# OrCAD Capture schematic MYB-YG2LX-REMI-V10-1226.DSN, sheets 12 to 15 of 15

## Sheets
12 PH-RPI & KEY & RTC: size A3; note: MISC
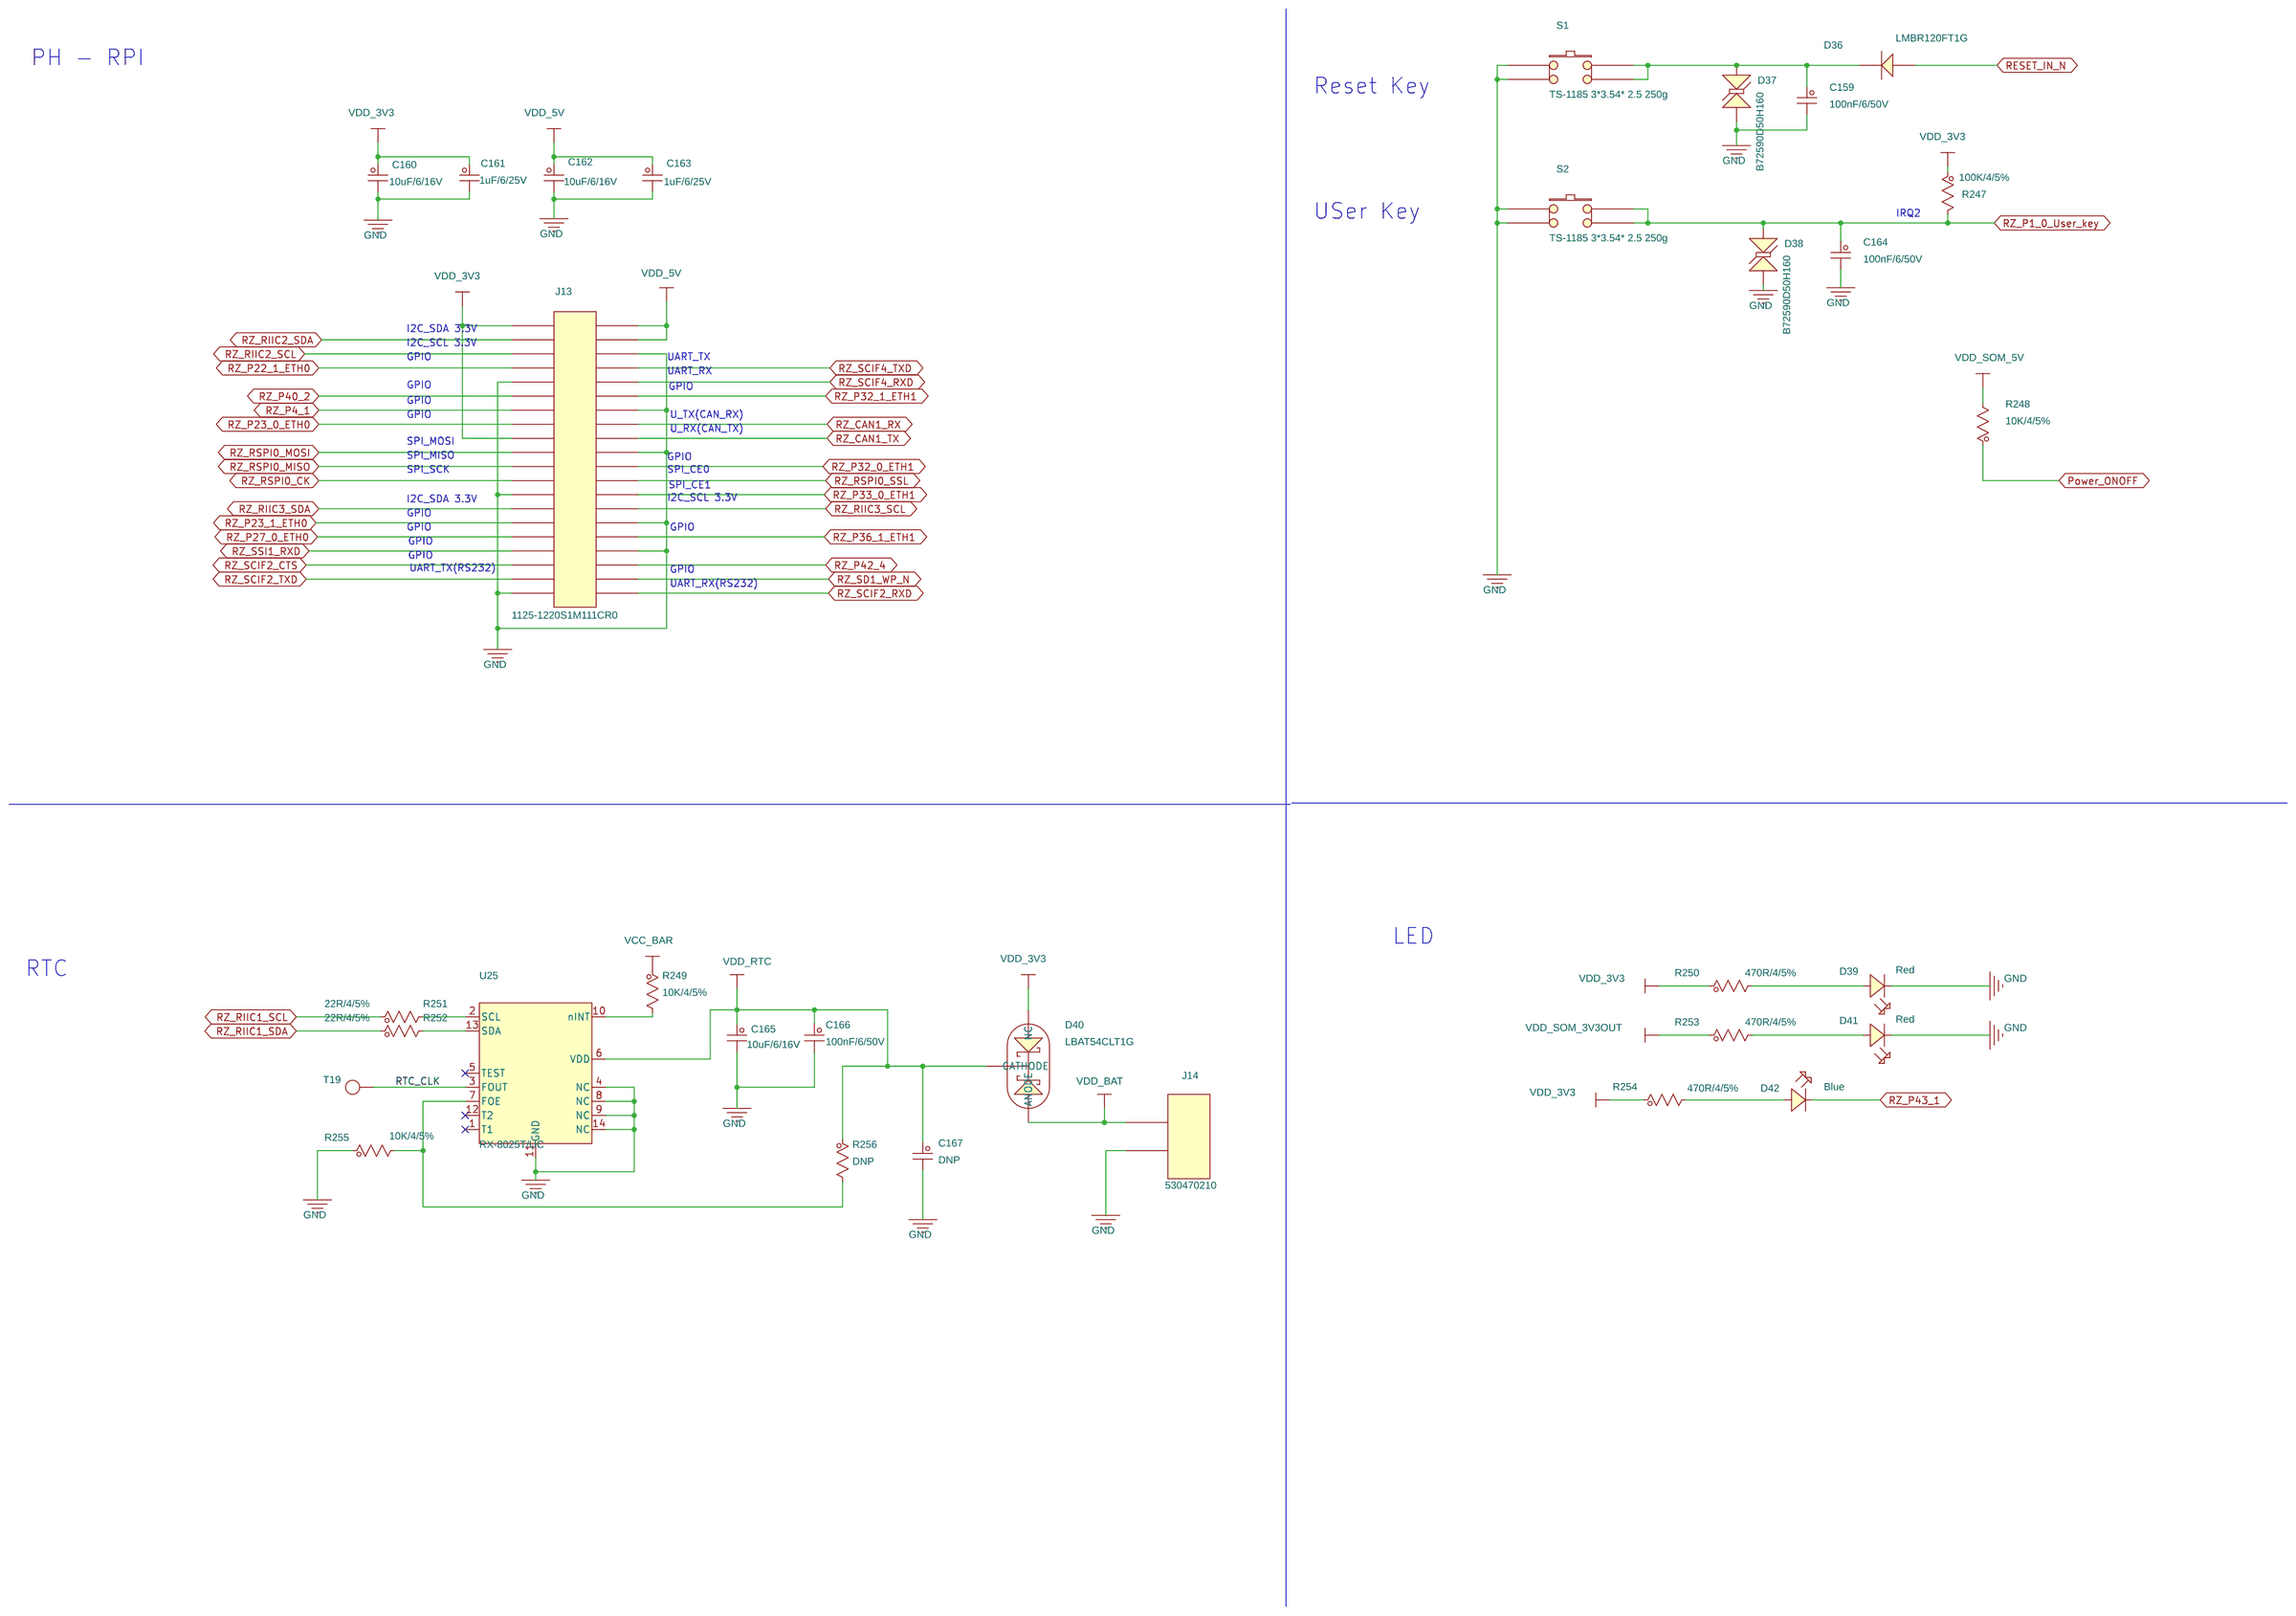
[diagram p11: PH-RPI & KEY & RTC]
13 Debug: size A3; note: Dispaly
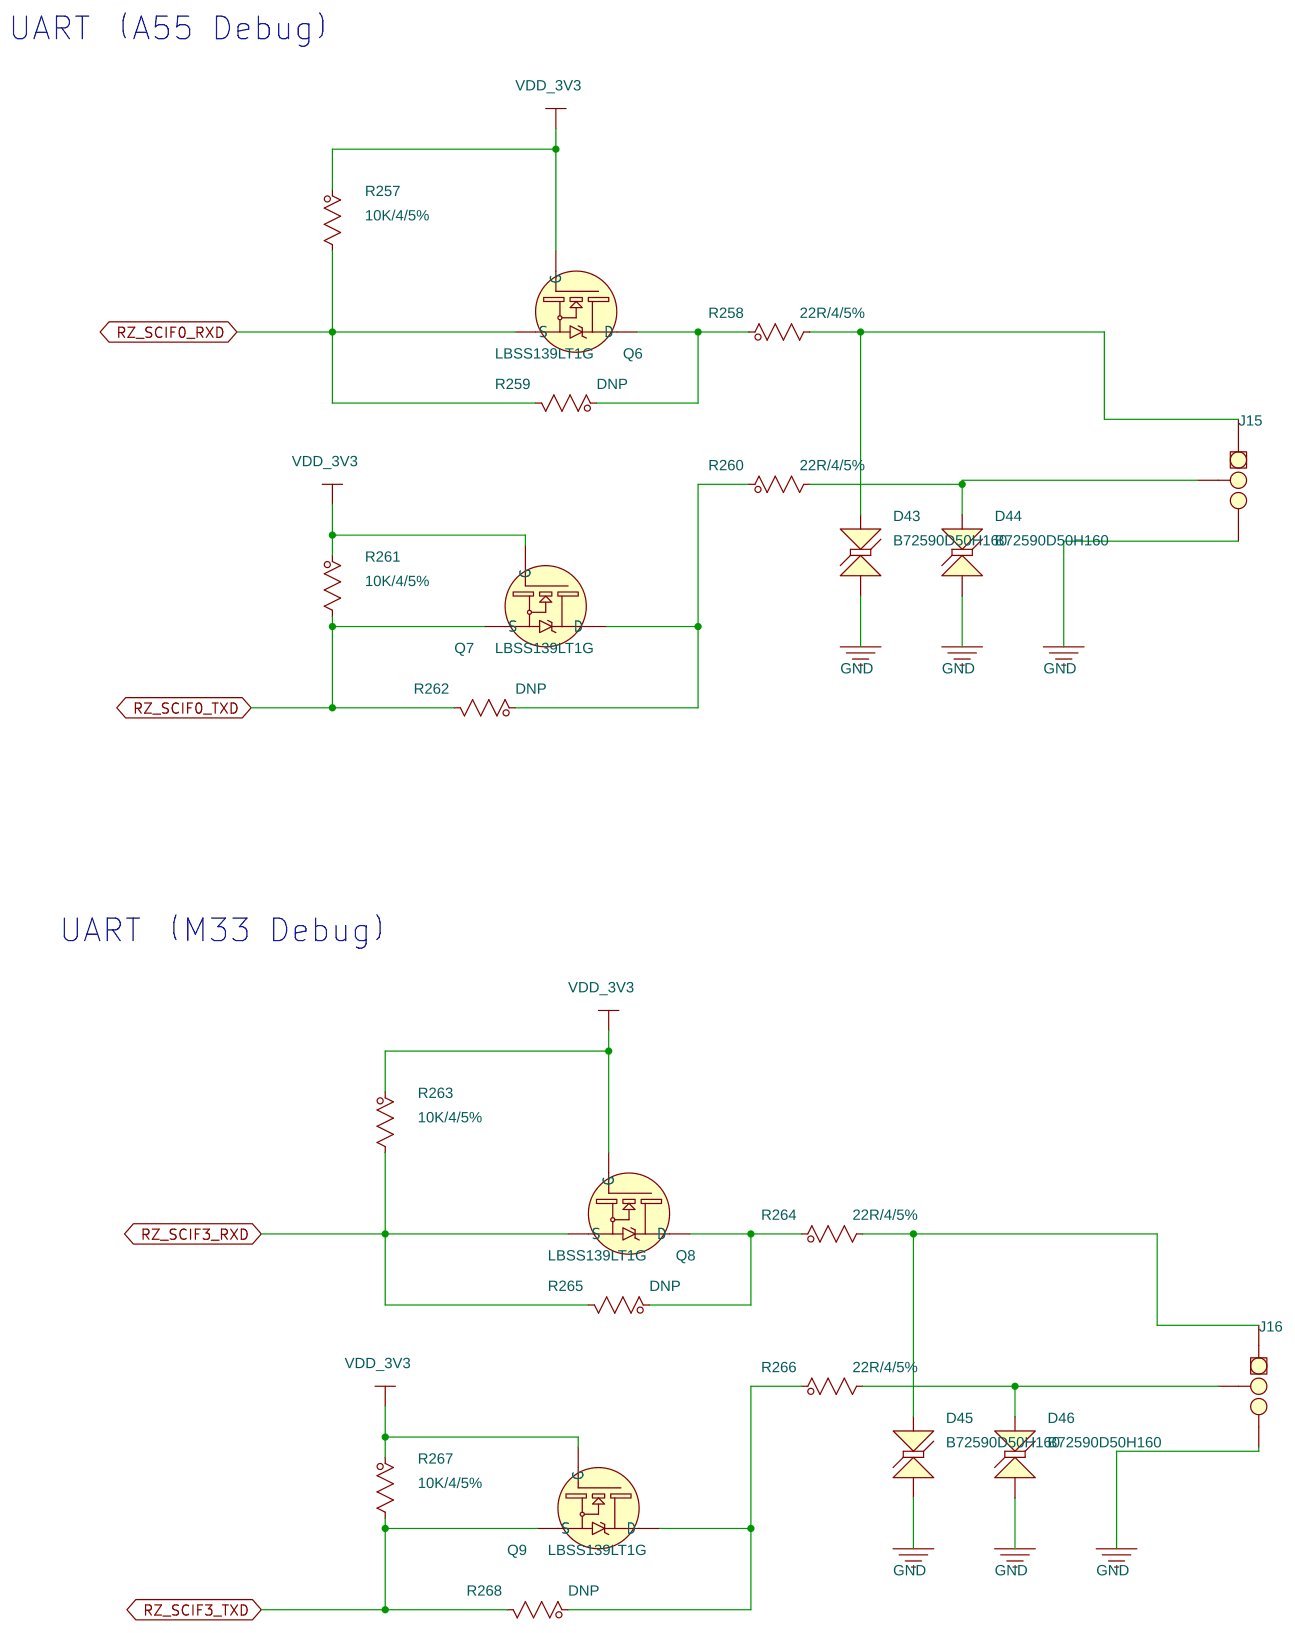
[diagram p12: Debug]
14 MYC Connector: size A2; note: MYC-YG2LX-SCH-V01
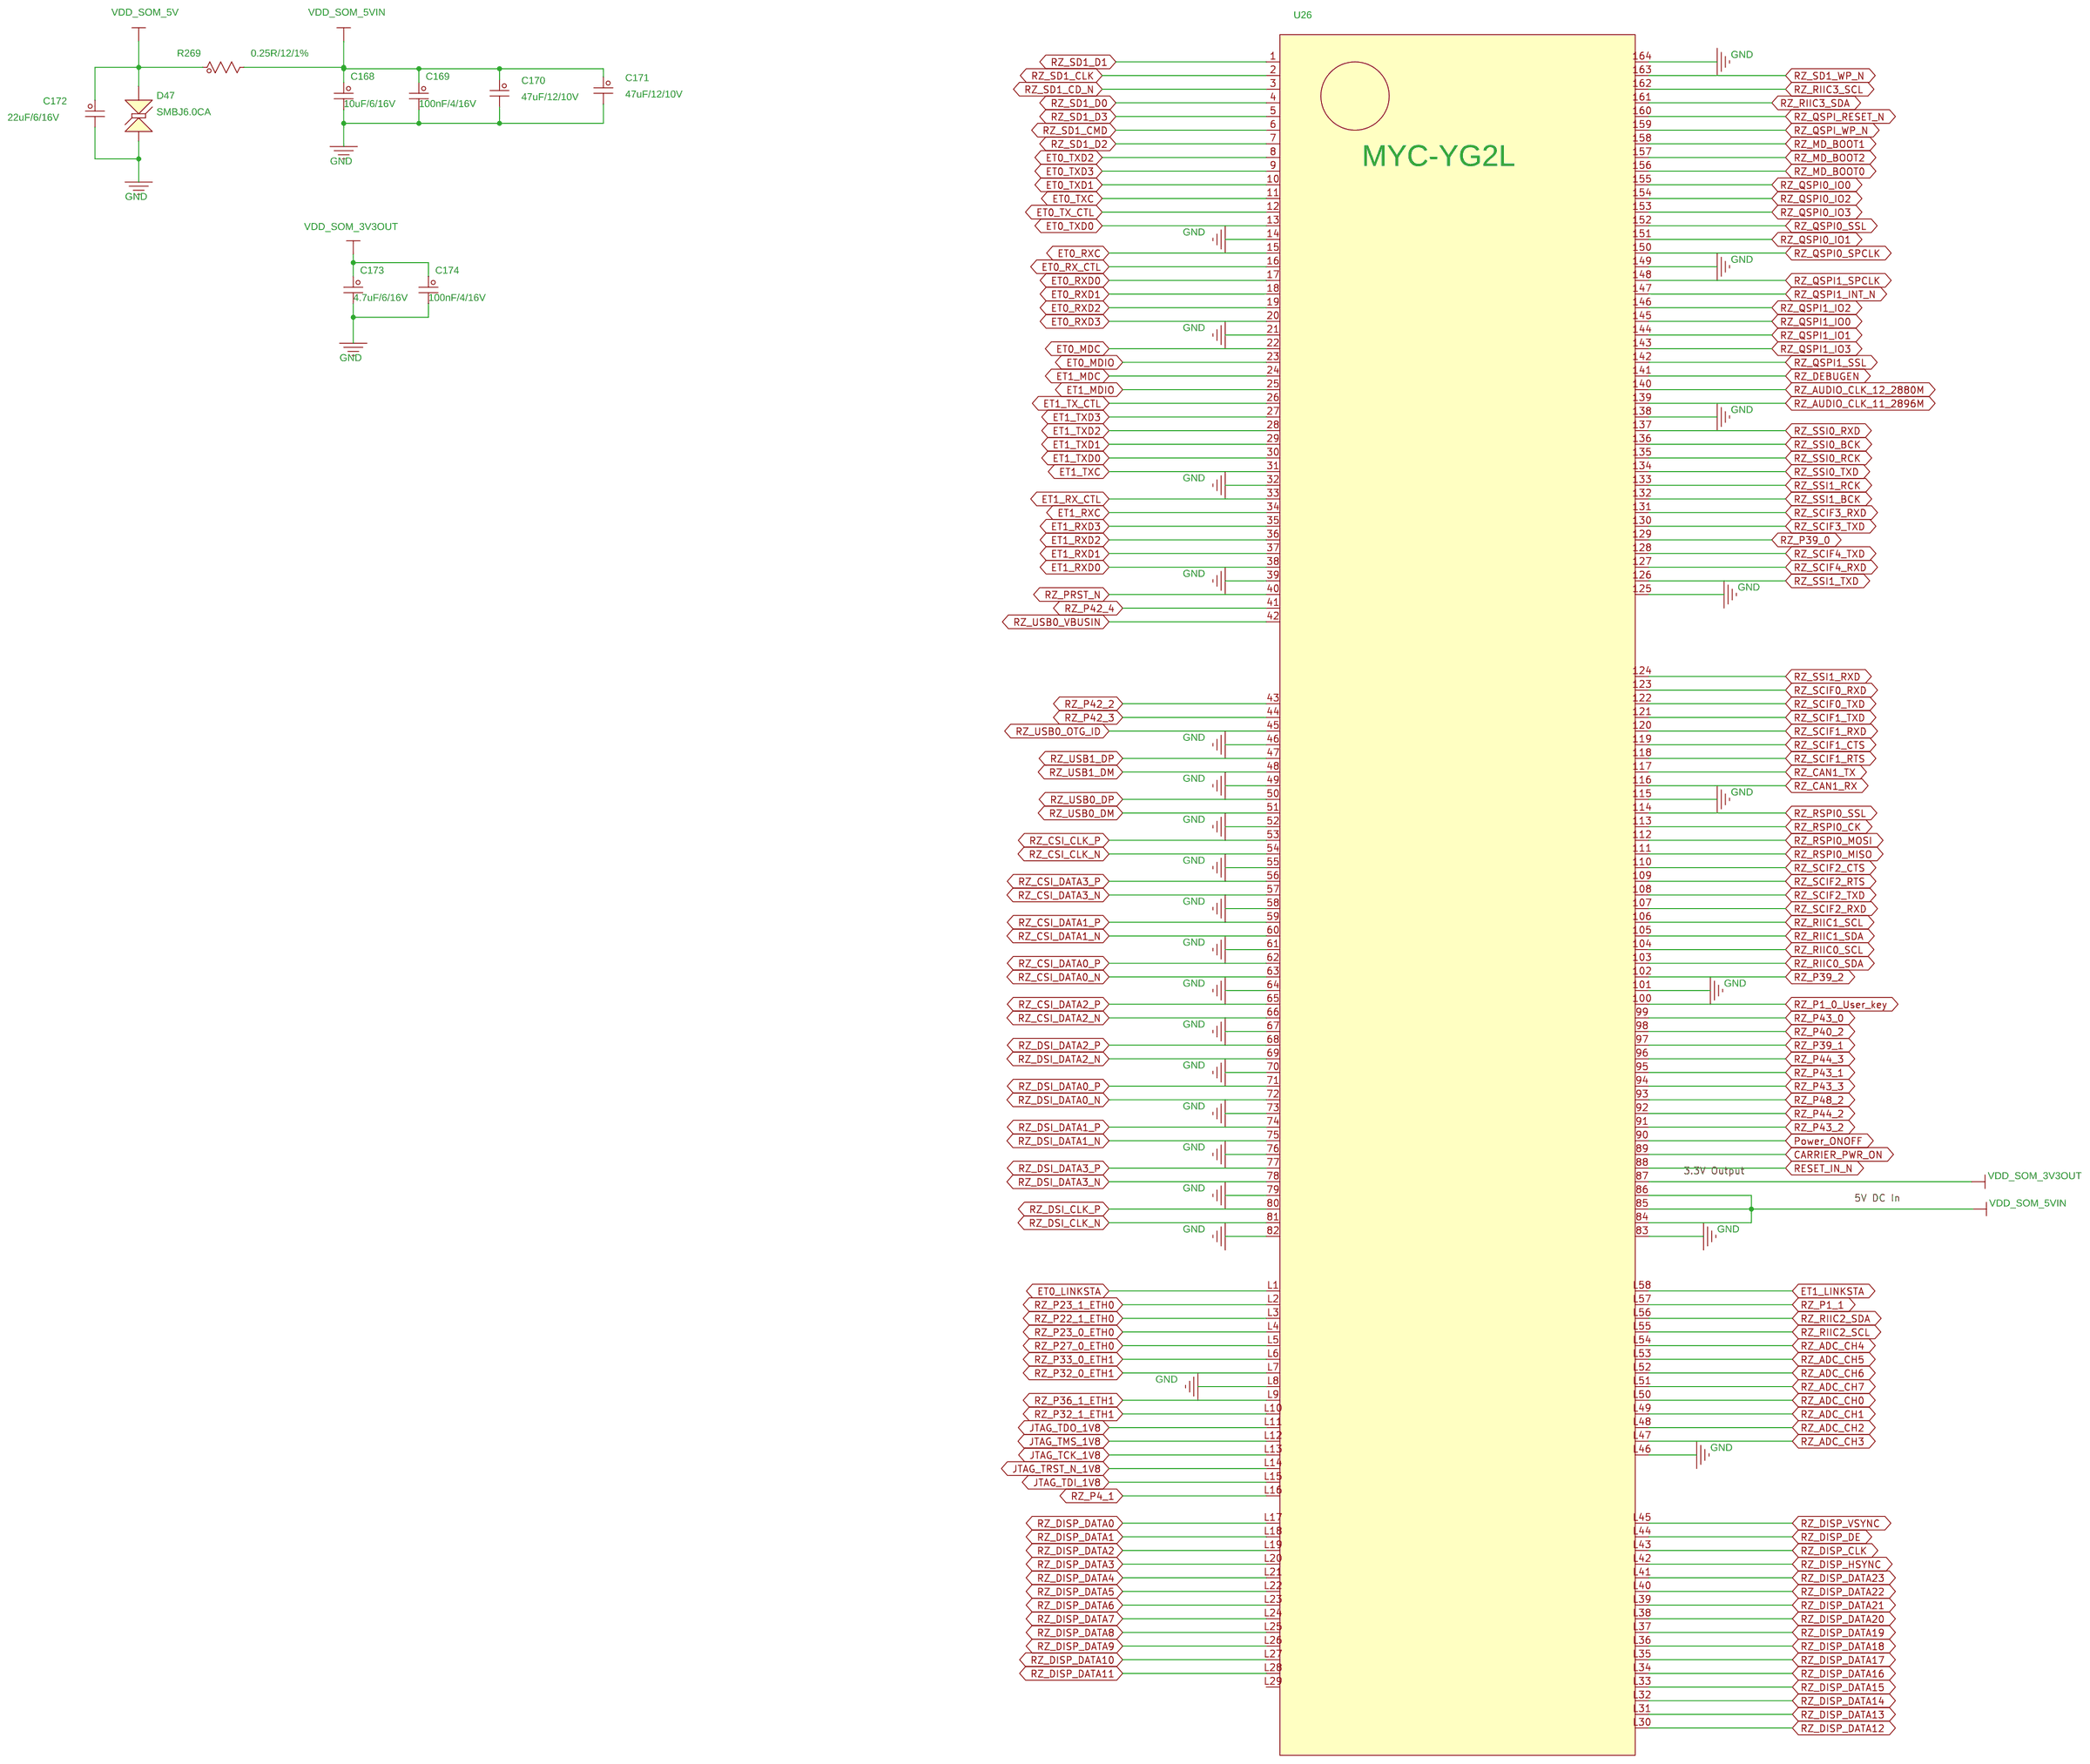
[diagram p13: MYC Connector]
15 Mechanical: size A3; note: Mechanical
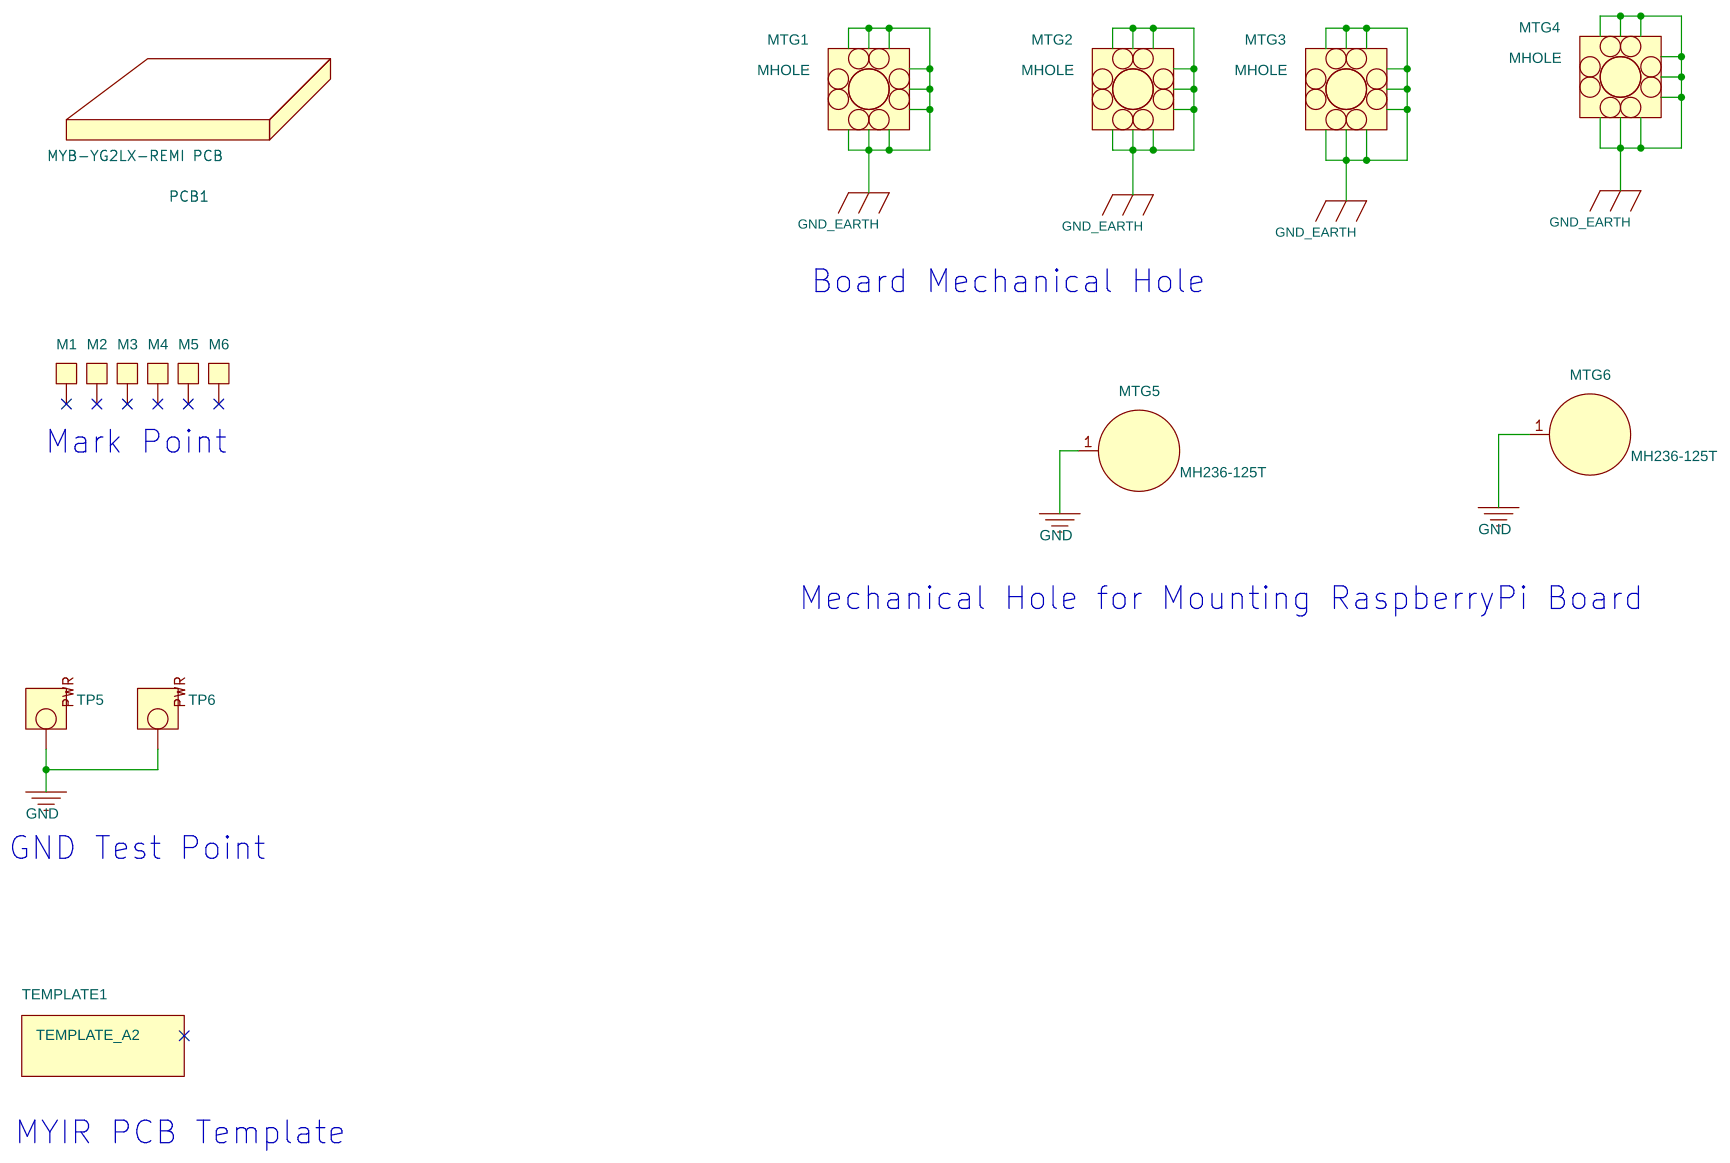
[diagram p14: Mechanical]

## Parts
sheet Debug
D43  B72590D50H160  [D0402]
D44  B72590D50H160  [D0402]
D45  B72590D50H160  [D0402]
D46  B72590D50H160  [D0402]
J15  1X3PIN-2_54  [CONN1x3-2_54-dip]
J16  1X3PIN-2_54  [CONN1x3-2_54-dip]
Q6  LBSS139LT1G  [SOT-23]
Q7  LBSS139LT1G  [SOT-23]
Q8  LBSS139LT1G  [SOT-23]
Q9  LBSS139LT1G  [SOT-23]
R257  10K/4/5%  [R0402]
R258  22R/4/5%  [R0402]
R259  DNP  [R0402]
R260  22R/4/5%  [R0402]
R261  10K/4/5%  [R0402]
R262  DNP  [R0402]
R263  10K/4/5%  [R0402]
R264  22R/4/5%  [R0402]
R265  DNP  [R0402]
R266  22R/4/5%  [R0402]
R267  10K/4/5%  [R0402]
R268  DNP  [R0402]
sheet Mechanical
M1  Mark Piont  [id-board]
M2  Mark Piont  [id-board]
M3  Mark Piont  [id-board]
M4  Mark Piont  [id-board]
M5  Mark Piont  [id-board]
M6  Mark Piont  [id-board]
MTG1  MHOLE  [hole3_2p-8]
MTG2  MHOLE  [hole3_2p-8]
MTG3  MHOLE  [hole3_2p-8]
MTG4  MHOLE  [hole3_2p-8]
MTG5  MH236-125T  [MH236-125T]
MTG6  MH236-125T  [MH236-125T]
PCB1  MYB-YG2LX-REMI PCB  [id-board]
TEMPLATE1  TEMPLATE_A2  [TEMPLATE-A2]
TP5  SMD  [HOLE-TP0_9S16]
TP6  SMD  [HOLE-TP0_9S16]
sheet MYC Connector
C168  10uF/6/16V  [C0603]
C169  100nF/4/16V  [C0402]
C170  47uF/12/10V  [C1206]
C171  47uF/12/10V  [C1206]
C172  22uF/6/16V  [C0603]
C173  4.7uF/6/16V  [C0603]
C174  100nF/4/16V  [C0402]
D47  SMBJ6.0CA  [DO-214AA]
R269  0.25R/12/1%  [R1206]
U26  MYC-YG2L  [myb-youpk43x45_1_00-lga58]
sheet PH-RPI & KEY & RTC
C159  100nF/6/50V  [C0603]
C160  10uF/6/16V  [C0603]
C161  1uF/6/25V  [C0603]
C162  10uF/6/16V  [C0603]
C163  1uF/6/25V  [C0603]
C164  100nF/6/50V  [C0603]
C165  10uF/6/16V  [C0603]
C166  100nF/6/50V  [C0603]
C167  DNP  [C0603]
D36  LMBR120FT1G  [SOD123]
D37  B72590D50H160  [D0402]
D38  B72590D50H160  [D0402]
D39  Red  [LED0805]
D40  LBAT54CLT1G  [SOT-23]
D41  Red  [LED0805]
D42  Blue  [LED0603]
J13  1125-1220S1M111CR0  [TSM-2d54-2x20p]
J14  530470210  [CONN1x2-1_25-dip]
R247  100K/4/5%  [R0402]
R248  10K/4/5%  [R0402]
R249  10K/4/5%  [R0402]
R250  470R/4/5%  [R0402]
R251  22R/4/5%  [R0402]
R252  22R/4/5%  [R0402]
R253  470R/4/5%  [R0402]
R254  470R/4/5%  [R0402]
R255  10K/4/5%  [R0402]
R256  DNP  [R0402]
S1  TS-1185 3*3.54* 2.5 250g  [key-3x4x2_5]
S2  TS-1185 3*3.54* 2.5 250g  [key-3x4x2_5]
T19  SMD  [test0_8-smd]
U25  RX-8025T/UC  [SOP14]

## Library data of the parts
D37 D38 D43-D46 = TVS_Diode: Diode,TVS,5.6VDC,SMD,D0402,TDK; Manufacturer: TDK; Myir P/N: 20701.00001; Part Type: Diode; Datasheet: B72590D0050H160.pdf
J15 J16 = SIP3-DROIT: Connector,PH,Straight,Male,1x3Pin,2.54mm,Pitch,PA6.0,PC3.0,Gold Flash 3u,black,DIP,GDZ; Manufacturer: GDZ; Manufacturer P/N: 12251103CNG4S115001; Myir P/N: 21101.00051; Part Type: Connector; Reserve Value: 12251103CNG4S115001; Datasheet: 12251106CNG4S115001 2.54 1x6P.pdf
Q6-Q9 = N-MOSFET: Mosfet,N-Channel,50V,0.2A,SMD,SOT-23,LRC; Manufacturer: LRC; Myir P/N: 20703.00012; Part Type: Mosfet; Datasheet: LBSS139LT1G.pdf
R248 R249 R255-R257 R261 R263 R267 = Resister: Thick Film Resistor,10K,+/-5%,1/16W,-55°C ~ 155°C,SMD,0402,Fenghua; Manufacturer: Fenghua; Manufacturer P/N: RC-02W103JT; Myir P/N: 20301.00199; Part Type: Thick Film Resistor; Reserve Value: 10K; Datasheet: FH规格书_2018-07-30.pdf
R258 R260 R264 R266 = Resister: Thick Film Resistor,22R,+/-5%,1/16W,-55°C ~ 155°C,SMD,0402,Fenghua; Manufacturer: Fenghua; Manufacturer P/N: RC-02W220JT; Myir P/N: 20301.00187; Part Type: Thick Film Resistor; Reserve Value: 22R; SIGNAL_MODEL: RESISTER_R0402_22/4/5%_22/4/5%; Datasheet: FH规格书_2018-07-30.pdf
R259 R262 R265 R268 = Resister: Thick Film Resistor,22R,+/-5%,1/16W,-55°C ~ 155°C,SMD,0402,Fenghua; Manufacturer: Fenghua; Manufacturer P/N: RC-02W220JT; Myir P/N: 20301.00187; Part Type: Thick Film Resistor; Reserve Value: 22R; Datasheet: FH规格书_2018-07-30.pdf
M1-M6 = TP_v2: DESIG: testing PAD; FAB: NA; REF: NA; VAL: NOT POPULATED
MTG1-MTG4 = MHOLE_3
MTG5 MTG6 = Mounting_Hole_1P: Mounting hole DRILL 125 CIRC PAD 236 PLATED THRU HOLE, NO PART TO ORDER; AGILE_PN: 280-77051; CAD_APPROVED: Yes; HEIGHT: 0.05 MM; MFG_NAME01: none; MFG_PN01: none; ROHS: Yes
PCB1 = PCB: Page: 31
TEMPLATE1 = TEMPLATE-A2: Manufacturer: MYIR; Myir P/N: 21122.00032XN; Part Type: Other
TP5 TP6 = TP_7: DESIG: testing PAD; FAB: NA; REF: NA; VAL: NOT POPULATED
C168 = Ceramic_Capacitor: Ceramic Capacitor,10uF,16V,+/-20%,X5R,0603,Samsung; Manufacturer: Samsung; Manufacturer P/N: CL10A106MONQNC; Myir P/N: 20401.80062; Part Type: Ceramic Capacitor; Reserve Value: 10uF; Datasheet: Samsung.pdf
C169 C174 = Ceramic_Capacitor: Ceramic Capacitor,100nF,16V,+/-10%,,X7R,0402,Fenghua; Manufacturer: Fenghua; Manufacturer P/N: 0402B104K160NT; Myir P/N: 20401.80188; Part Type: Ceramic Capacitor; Reserve Value: 100nF; Datasheet: FENGHUA-Capacitor.pdf
C170 C171 = Ceramic_Capacitor: Ceramic Capacitor,47uF,10V,+/-20%,X5R,1206,Samsung; Manufacturer: Samsung; Manufacturer P/N: CL31A476MPHNNNE; Myir P/N: 20401.80106; Part Type: Ceramic Capacitor; Reserve Value: 47uF; Datasheet: Samsung.pdf
C172 = Ceramic_Capacitor: Ceramic Capacitor,22uF,16V,+/-20%,X5R,0603,Reel,Fenghua; Manufacturer: Fenghua; Manufacturer P/N: 0603X226M160NT; Myir P/N: 20401.00103; Part Type: Ceramic Capacitor; Reserve Value: 22uF; Datasheet: FENGHUA-Capacitor.pdf
C173 = Ceramic_Capacitor: Ceramic Capacitor,4.7uF, 16V, +/-10%, X5R, 0603,Samsung; Manufacturer: Samsung; Manufacturer P/N: CL10A475KO8NNNC; Myir P/N: 20401.80066; Part Type: Ceramic Capacitor; Reserve Value: 4.7uF; Datasheet: Samsung.pdf
D47 = TVS_Diode: Diode, TVS Bi-Dir 6V 600W, DO-214AA(SMB); Manufacturer: UN; Myir P/N: 20701.00028; Part Type: Diode; Datasheet: SMBJ6.0C.pdf
R269 = Resister: Thick Film Resistor,0.25R,+/-1%,1/4W,-55°C ~ 155°C,SMD,1206,Fenghua; Manufacturer: Fenghua; Manufacturer P/N: RS-06MR250FT; Myir P/N: 20301.80403; Part Type: Thick Film Resistor; Reserve Value: 0.25R; Datasheet: FHsheet_2018-07-30.PDF
U26 = MYC-Y15X_0
C159 C164 C166 C167 = Ceramic_Capacitor: Ceramic Capacitor,100nF, 50V,+/-10%, X7R,0603,Fenghua; Manufacturer: Fenghua; Manufacturer P/N: 0603B104K500NT; Myir P/N: 20401.80129; Part Type: Ceramic Capacitor; Reserve Value: 100nF; Datasheet: FENGHUA-Capacitor.pdf
C160 C162 C165 = CERAMIC_CAPACITOR: Ceramic Capacitor,10uF,16V,+/-20%,X5R,0603,Samsung; Manufacturer: Samsung; Manufacturer P/N: CL10A106MONQNC; Myir P/N: 20401.80062; Part Type: Ceramic Capacitor; Reserve Value: 10uF; Datasheet: Samsung.pdf
C161 C163 = Ceramic_Capacitor: Ceramic Capacitor,1uF, 25V,+/-10%,X5R,0603,Samsung; Manufacturer: Samsung; Manufacturer P/N: CL10A105KA8NNNC; Myir P/N: 20401.80063; Part Type: Ceramic Capacitor; Reserve Value: 1uF; Datasheet: Samsung.pdf
D36 = General_Diode: Diode,Schottky Barrier Diode,20V,1A,SMD,SOD123L,LRC; Manufacturer: LRC; Myir P/N: 20701.00053; Part Type: Diode; Datasheet: LMBR120FT1G.pdf
D39 D41 = LED-17-21SURC_S530-A3_TR8: LED,Brilliant Red,Water Clear,20mA,SMD,0805,Everlight; Manufacturer: Everlight; Manufacturer P/N: 17-21SURC/S530-A3/TR8; Myir P/N: 20704.00003; Part Type: LED; Datasheet: 17-21SURC,S530-A3.pdf
D40 = BAT54C: Diode Dual Schottky,30V,200mA,SMD,SOT-23,LRC; Manufacturer: LRC; Myir P/N: 20701.00054; Part Type: Diode; Datasheet: LBAT54CLT1G.pdf
D42 = LED-19-217_BHC-ZL1M2RY_3T: LED,Brilliant Blue,Water Clear,10mA,SMD,0603,Everlight; Manufacturer: Everlight; Manufacturer P/N: 19-217/BHC-ZL1M2RY/3T; Myir P/N: 20704.00011; Part Type: LED; Datasheet: 19-217-BHC-ZL1M2RY-3T.pdf
J13 = 2X20PIN: Connector,Pin Header,Straight,Male,2X20Pin,2.54mm pitch,5.9,3.34,Gold Flash 1u, black,DIP,WCON; Manufacturer: WCON; Myir P/N: 21101.00049; Part Type: Connector; Datasheet: 1125-12XXXXMXXXCRXX.pdf
J14 = 1X2PIN: Board Connector,2 Pin,1.25 mm,1 Row(s), Male, Straight,-40 ~ +85 °C,Molex; Manufacturer: Molex; Myir P/N: 21110.00022; Part Type: Board Connector; Datasheet: RTC_conn_Molex_530470210.pdf
R247 = Resister: Thick Film Resistor,100K,+/-5%,,1/16W,-55°C ~ 155°C,SMD,0402,Fenghua; Manufacturer: Fenghua; Manufacturer P/N: RC-02W104JT; Myir P/N: 20301.00210; Part Type: Thick Film Resistor; Reserve Value: 100K; Datasheet: FHsheet_2018-07-30.PDF
R250 R253 R254 = Resister: Thick Film Resistor,470R,+/-5%,1/16W,-55°C ~ 155°C,SMD,0402,Fenghua; Manufacturer: Fenghua; Manufacturer P/N: RC-02W471JT; Myir P/N: 20301.00193; Part Type: Thick Film Resistor; Reserve Value: 470R; Datasheet: FH规格书_2018-07-30.pdf
R251 R252 = RESISTER: Thick Film Resistor,22R,+/-5%,1/16W,-55°C ~ 155°C,SMD,0402,Fenghua; Manufacturer: Fenghua; Manufacturer P/N: RC-02W220JT; Myir P/N: 20301.00187; Part Type: Thick Film Resistor; Reserve Value: 22R; Datasheet: FH规格书_2018-07-30.pdf
S1 S2 = KEY-TS-1109W: 3*3.54*2.5 Tact Switch,-16~60℃,额定电流:50mA,12V DC,绝缘电阻100mR min,BEST; Manufacturer: BEST; Myir P/N: 21201.00007; Part Type: Key; Datasheet: TS-1185 承认书.pdf
T19 = TP: DESIG: testing PAD; FAB: NA; REF: NA; VAL: NOT POPULATED
U25 = RX-8025T: IC,I2C-Bus Interface RTC Module,SMD,SOP14,Epson; Manufacturer: Epson; Myir P/N: 20108.00003; Part Type: Clock; RP1 Manufacturer P/N: XCRSE8025TIAD; RP1 Myir P/N: 20108.80003; Datasheet: RX-8025T.pdf

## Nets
GND: C159.2 C160.2 C161.2 C162.2 C163.2 C164.2 C165.2 C166.2 C167.2 C168.2 C169.2 C170.2 C171.2 C172.2 C173.2 C174.2 D37.1 D38.1 D39.2(K) D41.2(K) D43.1 D44.1 D45.1 D46.1 D47.2 J13.6 J13.9 J13.14 J13.20 J13.25 J13.30 J13.34 J13.39 J14.2 J15.3 J16.3 MTG5.1 MTG6.1 R255.1 S1.1 S1.2 S2.1 S2.2 TP5.1(TP) TP6.1(TP) U25.4(NC) U25.8(NC) U25.9(NC) U25.11(GND) U25.14(NC) U26.14 U26.21 U26.32 U26.39 U26.46 U26.49 U26.52 U26.55 U26.58 U26.61 U26.64 U26.67 U26.70 U26.73 U26.76 U26.79 U26.82 U26.83 U26.101 U26.115 U26.125 U26.138 U26.149 U26.164 U26.L8 U26.L46 ; also on sheet 4 5 6 7 8 9 10 11
GND_EARTH: MTG1.1(GND1) MTG1.2(GND2) MTG1.3(GND3) MTG1.4(GND4) MTG1.5(GND5) MTG1.6(GND6) MTG1.7(GND7) MTG1.8(GND8) MTG1.9(GND9) MTG2.1(GND1) MTG2.2(GND2) MTG2.3(GND3) MTG2.4(GND4) MTG2.5(GND5) MTG2.6(GND6) MTG2.7(GND7) MTG2.8(GND8) MTG2.9(GND9) MTG3.1(GND1) MTG3.2(GND2) MTG3.3(GND3) MTG3.4(GND4) MTG3.5(GND5) MTG3.6(GND6) MTG3.7(GND7) MTG3.8(GND8) MTG3.9(GND9) MTG4.1(GND1) MTG4.2(GND2) MTG4.3(GND3) MTG4.4(GND4) MTG4.5(GND5) MTG4.6(GND6) MTG4.7(GND7) MTG4.8(GND8) MTG4.9(GND9) ; also on sheet 4 6 8 10
VDD_3V3: C160.1 C161.1 D40.2(NC) J13.1 J13.17 Q6.1(G) Q7.1(G) Q8.1(G) Q9.1(G) R247.1 R249.1 R250.1 R254.1 R257.1 R261.1 R263.1 R267.1 ; also on sheet 4 5 6 7 8 9 10 11
VDD_5V: C162.1 C163.1 C172.1 D47.1 J13.2 J13.4 R248.2 R269.1 ; also on sheet 4 5 6 8
VDD_BAT: D40.1(ANODE) J14.1
VDD_RTC: C165.1 C166.1 C167.1 D40.3(CATHODE) R256.1 U25.6(VDD)
VDD_SOM_3V3OUT: C173.1 C174.1 R253.1 U26.87 ; also on sheet 7
VDD_SOM_5VIN: C168.1 C169.1 C170.1 C171.1 R269.2 U26.84 U26.85 U26.86
CARRIER_PWR_ON: U26.89 ; also on sheet 4
ET0_LINKSTA: U26.L1 ; also on sheet 9
ET0_MDC: U26.22 ; also on sheet 10
ET0_MDIO: U26.23 ; also on sheet 10
ET0_RX_CTL: U26.16 ; also on sheet 10
ET0_RXC: U26.15 ; also on sheet 10
ET0_RXD0: U26.17 ; also on sheet 10
ET0_RXD1: U26.18 ; also on sheet 10
ET0_RXD2: U26.19 ; also on sheet 10
ET0_RXD3: U26.20 ; also on sheet 10
ET0_TX_CTL: U26.12 ; also on sheet 10
ET0_TXC: U26.11 ; also on sheet 10
ET0_TXD0: U26.13 ; also on sheet 10
ET0_TXD1: U26.10 ; also on sheet 10
ET0_TXD2: U26.8 ; also on sheet 10
ET0_TXD3: U26.9 ; also on sheet 10
ET1_LINKSTA: U26.L58
ET1_MDC: U26.24 ; also on sheet 10
ET1_MDIO: U26.25 ; also on sheet 10
ET1_RX_CTL: U26.33 ; also on sheet 10
ET1_RXC: U26.34 ; also on sheet 10
ET1_RXD0: U26.38 ; also on sheet 10
ET1_RXD1: U26.37 ; also on sheet 10
ET1_RXD2: U26.36 ; also on sheet 10
ET1_RXD3: U26.35 ; also on sheet 10
ET1_TX_CTL: U26.26 ; also on sheet 10
ET1_TXC: U26.31 ; also on sheet 10
ET1_TXD0: U26.30 ; also on sheet 10
ET1_TXD1: U26.29 ; also on sheet 10
ET1_TXD2: U26.28 ; also on sheet 10
ET1_TXD3: U26.27 ; also on sheet 10
JTAG_TCK_1V8: U26.L13
JTAG_TDI_1V8: U26.L15
JTAG_TDO_1V8: U26.L11
JTAG_TMS_1V8: U26.L12
JTAG_TRST_N_1V8: U26.L14
Power_ONOFF: R248.1 U26.90
RESET_IN_N: D36.1 U26.88
RTC_CLK: T19.1(TP) U25.3(FOUT)
RZ_ADC_CH0: U26.L50
RZ_ADC_CH1: U26.L49
RZ_ADC_CH2: U26.L48
RZ_ADC_CH3: U26.L47
RZ_ADC_CH4: U26.L54
RZ_ADC_CH5: U26.L53
RZ_ADC_CH6: U26.L52
RZ_ADC_CH7: U26.L51
RZ_AUDIO_CLK_11_2896M: U26.139 ; also on sheet 9
RZ_AUDIO_CLK_12_2880M: U26.140 ; also on sheet 9
RZ_CAN1_RX: J13.16 U26.116
RZ_CAN1_TX: J13.18 U26.117
RZ_CSI_CLK_N: U26.54 ; also on sheet 5
RZ_CSI_CLK_P: U26.53 ; also on sheet 5
RZ_CSI_DATA0_N: U26.63 ; also on sheet 5
RZ_CSI_DATA0_P: U26.62 ; also on sheet 5
RZ_CSI_DATA1_N: U26.60 ; also on sheet 5
RZ_CSI_DATA1_P: U26.59 ; also on sheet 5
RZ_CSI_DATA2_N: U26.66 ; also on sheet 5
RZ_CSI_DATA2_P: U26.65 ; also on sheet 5
RZ_CSI_DATA3_N: U26.57 ; also on sheet 5
RZ_CSI_DATA3_P: U26.56 ; also on sheet 5
RZ_DEBUGEN: U26.141 ; also on sheet 7
RZ_DISP_CLK: U26.L43
RZ_DISP_DATA0: U26.L17 ; also on sheet 11
RZ_DISP_DATA1: U26.L18 ; also on sheet 11
RZ_DISP_DATA2: U26.L19
RZ_DISP_DATA3: U26.L20 ; also on sheet 11
RZ_DISP_DATA4: U26.L21 ; also on sheet 11
RZ_DISP_DATA5: U26.L22
RZ_DISP_DATA6: U26.L23 ; also on sheet 11
RZ_DISP_DATA7: U26.L24 ; also on sheet 11
RZ_DISP_DATA8: U26.L25 ; also on sheet 11
RZ_DISP_DATA9: U26.L26 ; also on sheet 11
RZ_DISP_DATA10: U26.L27
RZ_DISP_DATA11: U26.L28
RZ_DISP_DATA12: U26.L30
RZ_DISP_DATA13: U26.L31
RZ_DISP_DATA14: U26.L32
RZ_DISP_DATA15: U26.L33
RZ_DISP_DATA16: U26.L34
RZ_DISP_DATA17: U26.L35
RZ_DISP_DATA18: U26.L36
RZ_DISP_DATA19: U26.L37
RZ_DISP_DATA20: U26.L38 ; also on sheet 5
RZ_DISP_DATA21: U26.L39
RZ_DISP_DATA22: U26.L40 ; also on sheet 11
RZ_DISP_DATA23: U26.L41 ; also on sheet 11
RZ_DISP_DE: U26.L44
RZ_DISP_HSYNC: U26.L42
RZ_DISP_VSYNC: U26.L45
RZ_DSI_CLK_N: U26.81 ; also on sheet 8
RZ_DSI_CLK_P: U26.80 ; also on sheet 8
RZ_DSI_DATA0_N: U26.72 ; also on sheet 8
RZ_DSI_DATA0_P: U26.71 ; also on sheet 8
RZ_DSI_DATA1_N: U26.75 ; also on sheet 8
RZ_DSI_DATA1_P: U26.74 ; also on sheet 8
RZ_DSI_DATA2_N: U26.69 ; also on sheet 8
RZ_DSI_DATA2_P: U26.68 ; also on sheet 8
RZ_DSI_DATA3_N: U26.78 ; also on sheet 8
RZ_DSI_DATA3_P: U26.77 ; also on sheet 8
RZ_MD_BOOT0: U26.156 ; also on sheet 7
RZ_MD_BOOT1: U26.158 ; also on sheet 7
RZ_MD_BOOT2: U26.157 ; also on sheet 7
RZ_P1_0_User_key: C164.1 D38.2 R247.2 S2.3 S2.4 U26.100
RZ_P1_1: U26.L57 ; also on sheet 6
RZ_P4_1: J13.13 U26.L16
RZ_P22_1_ETH0: J13.7 U26.L3
RZ_P23_0_ETH0: J13.15 U26.L4
RZ_P23_1_ETH0: J13.29 U26.L2
RZ_P27_0_ETH0: J13.31 U26.L5
RZ_P32_0_ETH1: J13.22 U26.L7
RZ_P32_1_ETH1: J13.12 U26.L10
RZ_P33_0_ETH1: J13.26 U26.L6
RZ_P36_1_ETH1: J13.32 U26.L9
RZ_P39_0: U26.129 ; also on sheet 5
RZ_P39_1: U26.97 ; also on sheet 5
RZ_P39_2: U26.102 ; also on sheet 5
RZ_P40_2: J13.11 U26.98
RZ_P42_2: U26.43 ; also on sheet 5
RZ_P42_3: U26.44 ; also on sheet 8
RZ_P42_4: J13.36 U26.41
RZ_P43_0: U26.99 ; also on sheet 8
RZ_P43_1: D42.2(K) U26.95
RZ_P43_2: U26.91 ; also on sheet 10
RZ_P43_3: U26.94 ; also on sheet 10
RZ_P44_2: U26.92 ; also on sheet 10
RZ_P44_3: U26.96 ; also on sheet 10
RZ_P48_2: U26.93 ; also on sheet 8
RZ_PRST_N: U26.40
RZ_QSPI0_IO0: U26.155
RZ_QSPI0_IO1: U26.151
RZ_QSPI0_IO2: U26.154
RZ_QSPI0_IO3: U26.153
RZ_QSPI0_SPCLK: U26.150
RZ_QSPI0_SSL: U26.152
RZ_QSPI1_INT_N: U26.147
RZ_QSPI1_IO0: U26.145
RZ_QSPI1_IO1: U26.144
RZ_QSPI1_IO2: U26.146
RZ_QSPI1_IO3: U26.143
RZ_QSPI1_SPCLK: U26.148
RZ_QSPI1_SSL: U26.142
RZ_QSPI_RESET_N: U26.160
RZ_QSPI_WP_N: U26.159
RZ_RIIC0_SCL: U26.104 ; also on sheet 5 6 8
RZ_RIIC0_SDA: U26.103 ; also on sheet 5 6 8
RZ_RIIC1_SCL: R251.1 U26.106 ; also on sheet 8 9
RZ_RIIC1_SDA: R252.1 U26.105 ; also on sheet 8 9
RZ_RIIC2_SCL: J13.5 U26.L55
RZ_RIIC2_SDA: J13.3 U26.L56
RZ_RIIC3_SCL: J13.28 U26.162
RZ_RIIC3_SDA: J13.27 U26.161
RZ_RSPI0_CK: J13.23 U26.113
RZ_RSPI0_MISO: J13.21 U26.111
RZ_RSPI0_MOSI: J13.19 U26.112
RZ_RSPI0_SSL: J13.24 U26.114
RZ_SCIF0_RXD: Q6.2(S) R257.2 R259.2 U26.123
RZ_SCIF0_TXD: Q7.2(S) R261.2 R262.2 U26.122
RZ_SCIF1_CTS: U26.119 ; also on sheet 11
RZ_SCIF1_RTS: U26.118 ; also on sheet 11
RZ_SCIF1_RXD: U26.120 ; also on sheet 11
RZ_SCIF1_TXD: U26.121 ; also on sheet 11
RZ_SCIF2_CTS: J13.35 U26.110
RZ_SCIF2_RTS: U26.109
RZ_SCIF2_RXD: J13.40 U26.107
RZ_SCIF2_TXD: J13.37 U26.108
RZ_SCIF3_RXD: Q8.2(S) R263.2 R265.2 U26.131
RZ_SCIF3_TXD: Q9.2(S) R267.2 R268.2 U26.130
RZ_SCIF4_RXD: J13.10 U26.127
RZ_SCIF4_TXD: J13.8 U26.128
RZ_SD1_CD_N: U26.3 ; also on sheet 7
RZ_SD1_CLK: U26.2 ; also on sheet 11
RZ_SD1_CMD: U26.6 ; also on sheet 11
RZ_SD1_D0: U26.4 ; also on sheet 11
RZ_SD1_D1: U26.1 ; also on sheet 11
RZ_SD1_D2: U26.7 ; also on sheet 11
RZ_SD1_D3: U26.5 ; also on sheet 11
RZ_SD1_WP_N: J13.38 U26.163
RZ_SSI0_BCK: U26.136 ; also on sheet 9
RZ_SSI0_RCK: U26.135 ; also on sheet 9
RZ_SSI0_RXD: U26.137 ; also on sheet 9
RZ_SSI0_TXD: U26.134 ; also on sheet 9
RZ_SSI1_BCK: U26.132 ; also on sheet 5
RZ_SSI1_RCK: U26.133 ; also on sheet 5
RZ_SSI1_RXD: J13.33 U26.124
RZ_SSI1_TXD: U26.126 ; also on sheet 5
RZ_USB0_DM: U26.51 ; also on sheet 6
RZ_USB0_DP: U26.50 ; also on sheet 6
RZ_USB0_OTG_ID: U26.45 ; also on sheet 6
RZ_USB0_VBUSIN: U26.42 ; also on sheet 6
RZ_USB1_DM: U26.48 ; also on sheet 6
RZ_USB1_DP: U26.47 ; also on sheet 6
N23602849: C159.1 D36.2 D37.2 S1.3 S1.4
N23945057: D39.1(A) R250.2
N23945063: D42.1(A) R254.2
N23950761: R255.2 R256.2 U25.7(FOE)
N23950837: R252.2 U25.13(SDA)
N23950839: R251.2 U25.2(SCL)
N25392814: D41.1(A) R253.2
N25800737: R249.2 U25.10(nINT)
N26098482: D44.2 J15.2 R260.2
N26098494: D43.2 J15.1 R258.2
N26098528: Q6.3(D) R258.1 R259.1
N26098578: Q7.3(D) R260.1 R262.1
N26103216: D46.2 J16.2 R266.2
N26103218: D45.2 J16.1 R264.2
N26103260: Q8.3(D) R264.1 R265.1
N26103310: Q9.3(D) R266.1 R268.1

Not connected (* = marked no-connect by the designer): M1 1*; M2 1*; M3 1*; M4 1*; M5 1*; M6 1*; TEMPLATE1 1*; U25 1(T1)* 5(TEST)* 12(T2)*; U26 L29

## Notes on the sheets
sheet 12
- PH - RPI
- Reset Key
- USer Key
- IRQ2
- I2C_SCL 3.3V
- I2C_SDA 3.3V
- GPIO
- UART_TX
- UART_RX
- GPIO
- GPIO
- GPIO
- GPIO
- U_TX(CAN_RX)
- SPI_MOSI
- U_RX(CAN_TX)
- SPI_MISO
- GPIO
- SPI_SCK
- SPI_CE0
- SPI_CE1
- I2C_SDA 3.3V
- I2C_SCL 3.3V
- GPIO
- GPIO
- GPIO
- GPIO
- GPIO
- UART_TX(RS232)
- GPIO
- UART_RX(RS232)
- LED
- RTC
sheet 13
- UART （A55 Debug）
- UART （M33 Debug）
sheet 14
- 3.3V Output
- 5V DC In
sheet 15
- Board Mechanical Hole
- Mark Point
- Mechanical Hole for Mounting RaspberryPi Board
- GND Test Point
- MYIR PCB Template
